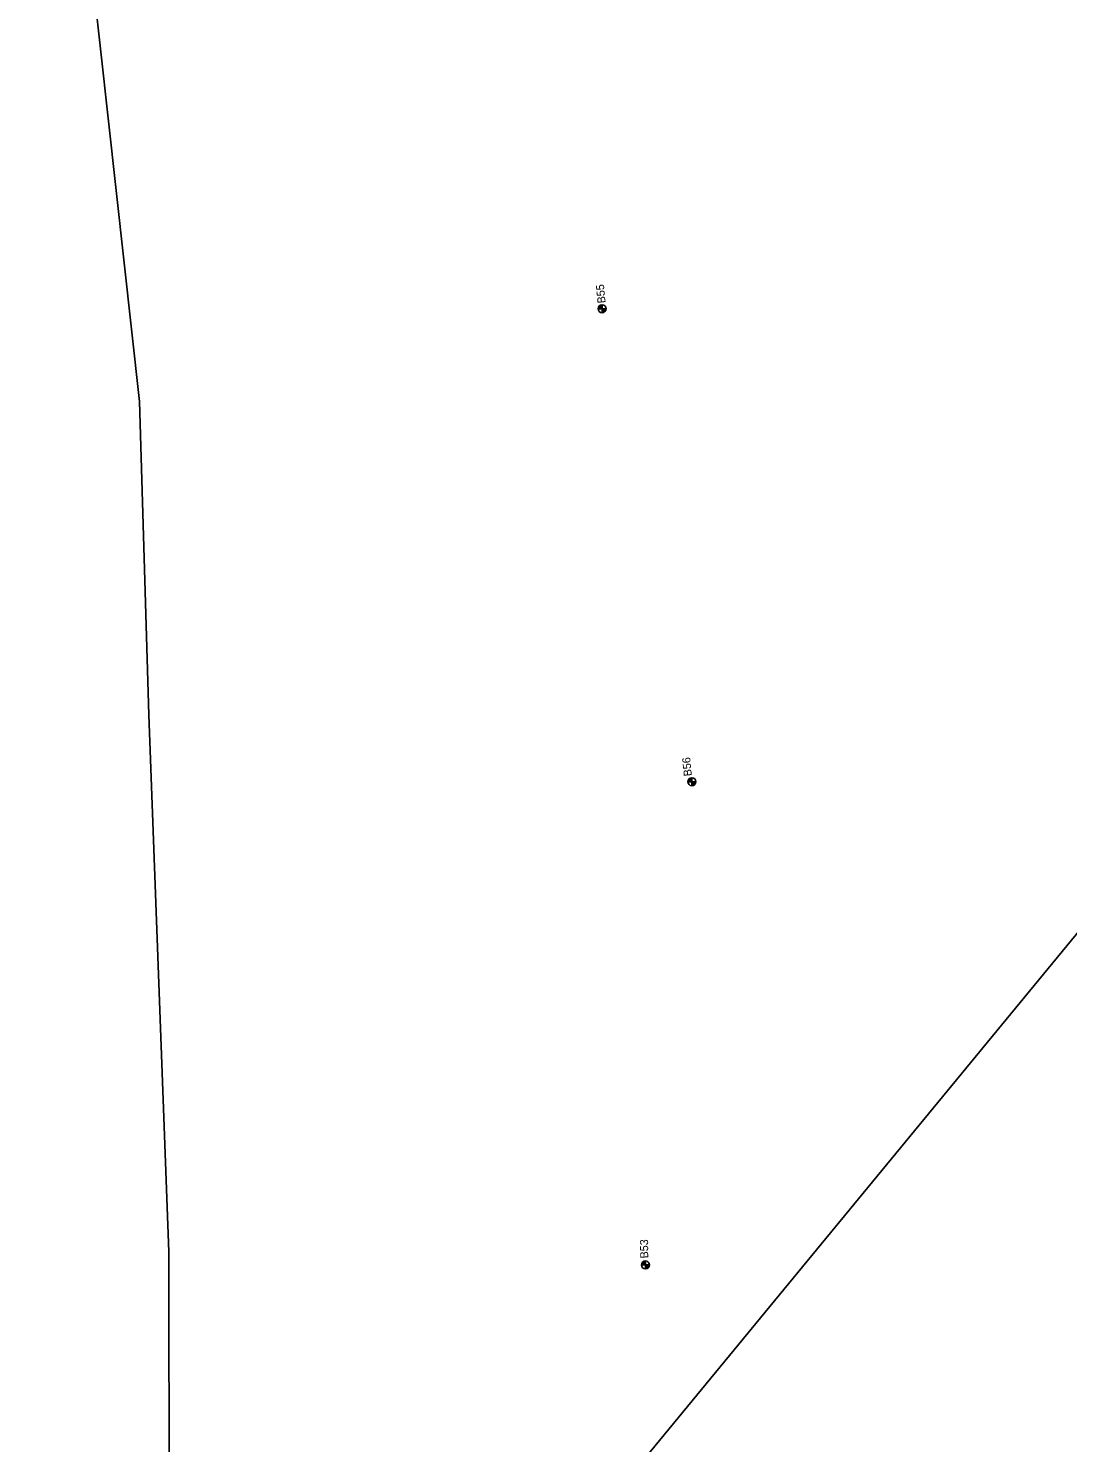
# Model space of a CAD drawing. Extents: x 311409 to 379449, y 121539 to 224848.
# Drawn here: x 359420 to 360718, y 159110 to 160877 of the extents above; entities that cross this region are included whole.
import ezdxf

# ---------------------------------------------------------------- set-up
doc = ezdxf.new("R2010")
doc.units = 0
for name, color, linetype in [('CA-TEXT', 7, 'Continuous'), ('E_SOIL_BORE1 [KAPUR_CADDS_LEVELS]', 7, 'Continuous'), ('E_SOIL_BORE2 [KAPUR_CADDS_LEVELS]', 7, 'Continuous'), ('P_MARK', 7, 'Continuous'), ('P_TC', 7, 'Continuous')]:
    doc.layers.add(name, color=color, linetype=linetype)

msp = doc.modelspace()

# ---------------------------------------------------------------- linework, layer by layer
at = {"layer": 'CA-TEXT'}
msp.add_line((364139.7, 163891.7), (359543.4, 158305.3), dxfattribs=at)
at = {"layer": 'P_MARK'}
for p, q in [((360131.3, 160526.6), (360141.3, 160526.6)), ((360136.3, 160531.6), (360136.3, 160521.6)), ((360243.3, 159935.8), (360253.3, 159935.8)), ((360248.3, 159940.8), (360248.3, 159930.8)), ((360190.4, 159337.2), (360190.4, 159327.2)), ((360185.4, 159332.2), (360195.4, 159332.2))]:
    msp.add_line(p, q, dxfattribs=at)
for centre in [(360136.3, 160526.6), (360248.3, 159935.8), (360190.4, 159332.2)]:
    msp.add_circle(centre, 5, dxfattribs=at)
for centre, radius, start, end in [((360136.3, 160526.6), 4.5, 89.9869, 179.9869), ((360136.3, 160526.6), 4, 89.9869, 179.9869), ((360136.3, 160526.6), 3.5, 89.9869, 179.9869), ((360136.3, 160526.6), 3, 89.9869, 179.9869), ((360136.3, 160526.6), 2.5, 89.9869, 179.9869), ((360136.3, 160526.6), 2, 89.9869, 179.9869), ((360136.3, 160526.6), 1.5, 89.9869, 179.9869), ((360136.3, 160526.6), 1, 89.9869, 179.9869), ((360136.3, 160526.6), 0.5, 89.9869, 179.9869), ((360136.3, 160526.6), 4.5, 269.9869, 359.9869), ((360136.3, 160526.6), 4, 269.9869, 359.9869), ((360136.3, 160526.6), 3.5, 269.9869, 359.9869), ((360136.3, 160526.6), 3, 269.9869, 359.9869), ((360136.3, 160526.6), 2.5, 269.9869, 359.9869), ((360136.3, 160526.6), 2, 269.9869, 359.9869), ((360136.3, 160526.6), 1.5, 269.9869, 359.9869), ((360136.3, 160526.6), 1, 269.9869, 359.9869), ((360136.3, 160526.6), 0.5, 269.9869, 359.9869), ((360248.3, 159935.8), 4.5, 89.9869, 179.9869), ((360248.3, 159935.8), 4, 89.9869, 179.9869), ((360248.3, 159935.8), 3.5, 89.9869, 179.9869), ((360248.3, 159935.8), 3, 89.9869, 179.9869), ((360248.3, 159935.8), 2.5, 89.9869, 179.9869), ((360248.3, 159935.8), 2, 89.9869, 179.9869), ((360248.3, 159935.8), 1.5, 89.9869, 179.9869), ((360248.3, 159935.8), 1, 89.9869, 179.9869), ((360248.3, 159935.8), 0.5, 89.9869, 179.9869), ((360248.3, 159935.8), 4.5, 269.9869, 359.9869), ((360248.3, 159935.8), 4, 269.9869, 359.9869), ((360248.3, 159935.8), 3.5, 269.9869, 359.9869), ((360248.3, 159935.8), 3, 269.9869, 359.9869), ((360248.3, 159935.8), 2.5, 269.9869, 359.9869), ((360248.3, 159935.8), 2, 269.9869, 359.9869), ((360248.3, 159935.8), 1.5, 269.9869, 359.9869), ((360248.3, 159935.8), 1, 269.9869, 359.9869), ((360248.3, 159935.8), 0.5, 269.9869, 359.9869), ((360190.4, 159332.2), 4.5, 89.9869, 179.9869), ((360190.4, 159332.2), 4, 89.9869, 179.9869), ((360190.4, 159332.2), 3.5, 89.9869, 179.9869), ((360190.4, 159332.2), 3, 89.9869, 179.9869), ((360190.4, 159332.2), 2.5, 89.9869, 179.9869), ((360190.4, 159332.2), 2, 89.9869, 179.9869), ((360190.4, 159332.2), 1.5, 89.9869, 179.9869), ((360190.4, 159332.2), 1, 89.9869, 179.9869), ((360190.4, 159332.2), 0.5, 89.9869, 179.9869), ((360190.4, 159332.2), 4.5, 269.9869, 359.9869), ((360190.4, 159332.2), 4, 269.9869, 359.9869), ((360190.4, 159332.2), 3.5, 269.9869, 359.9869), ((360190.4, 159332.2), 3, 269.9869, 359.9869), ((360190.4, 159332.2), 2.5, 269.9869, 359.9869), ((360190.4, 159332.2), 2, 269.9869, 359.9869), ((360190.4, 159332.2), 1.5, 269.9869, 359.9869), ((360190.4, 159332.2), 1, 269.9869, 359.9869), ((360190.4, 159332.2), 0.5, 269.9869, 359.9869)]:
    msp.add_arc(centre, radius, start, end, dxfattribs=at)
at = {"layer": 'P_TC'}
msp.add_lwpolyline([(358874.4, 163917.9), (359033, 163240.2), (359272.2, 162086.7), (359500.6, 160938.4), (359558.7, 160410.8), (359570.3, 160019.2), (359595.2, 159348.4), (359596, 158698.2), (359602.4, 153949.6), (359759.4, 152437.1), (359827.1, 151981.3), (359969.9, 151461.4), (360646.7, 148684.4)], dxfattribs=at)

# ---------------------------------------------------------------- texts
at = {"layer": 'E_SOIL_BORE1 [KAPUR_CADDS_LEVELS]'}
msp.add_text('B53', height=10, rotation=90.6368, dxfattribs=at).set_placement((360193.9, 159340.4))
at = {"layer": 'E_SOIL_BORE2 [KAPUR_CADDS_LEVELS]'}
for s, p in [('B55', (360140.7, 160533.9)), ('B56', (360248.4, 159943.1))]:
    msp.add_text(s, height=10, rotation=95.5802, dxfattribs=at).set_placement(p)

doc.saveas('drawing.dxf')
